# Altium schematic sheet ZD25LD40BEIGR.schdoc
size 127 x 101 mm
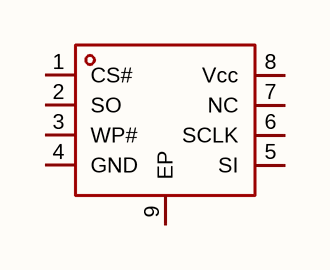
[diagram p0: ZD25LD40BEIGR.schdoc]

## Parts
U?  zd25ld40beigr  [USON-8_L3.0-W2.0-P0.50-BL-EP]  (value not drawn)

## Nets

Not connected (* = marked no-connect by the designer): U? 1(CS#) 2(SO) 3(WP#) 4(GND) 5(SI) 6(SCLK) 7(NC) 8(Vcc) 9(EP)

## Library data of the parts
U? = zd25ld40beigr: 接口类型:SPI;存储容量:4Mbit;时钟频率(fc):85MHz;; Manufacturer: Zetta(澜智); AddInBom: yes; ModelId: 2b35e1c3dcc44b77887d4f445b51370a; ModelName: USON-8_L2-W3-H0.6X0.5P; ModelTransform: 79.527,118.8974,0,0,0,0,-0.313,-1.1,0; Interface: SPI; Memory Size: 4Mbit; Clock Frequency: 85MHz; Voltage - Supply: 1.65V~2V; Standby Supply Current: 9uA; Program / Erase Cycles: 100000次; Write Cycle Time (tWC): 8ms; Page Programming Time (Tpp): 1.6ms; Block Erase Time(tBE): 10ms; Data Retention - TDR (Year): 20年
